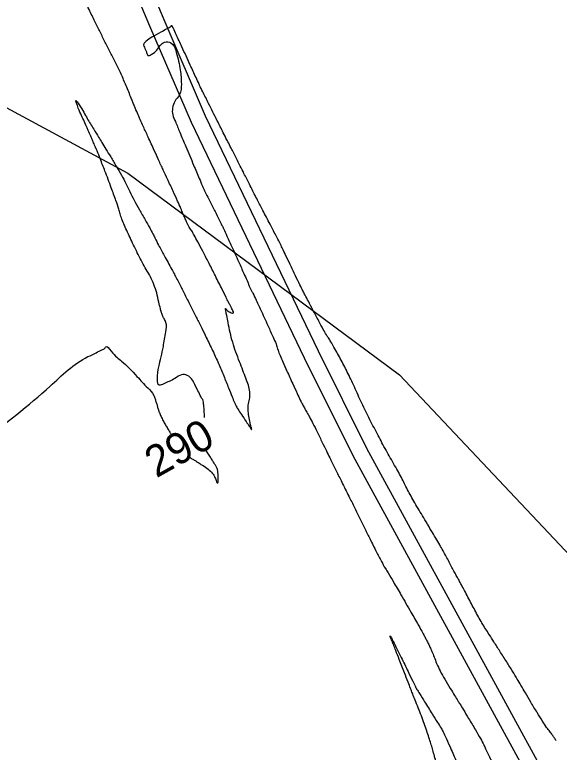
# Model space of a CAD drawing. Extents: x -478464 to -472469, y -1118040 to -1113785.
# Drawn here: x -473768.3 to -473698.4, y -1115256.6 to -1115161.8 of the extents above; entities that cross this region are included whole.
import ezdxf

# ---------------------------------------------------------------- set-up
doc = ezdxf.new("R2010")
doc.units = 0
for name, color, linetype in [('povodí', 7, 'Continuous'), ('Vrstevnice_hlavni', 7, 'Continuous'), ('Vrstevnice_popis', 7, 'Continuous'), ('Vrstevnice_vedlejsi', 7, 'Continuous'), ('zeleznice', 7, 'Continuous')]:
    doc.layers.add(name, color=color, linetype=linetype)

msp = doc.modelspace()

# ---------------------------------------------------------------- linework, layer by layer
at = {"layer": 'povodí'}
msp.add_lwpolyline([(-473844.074, -1115133.113), (-473798.595, -1115157.979), (-473753.827, -1115182.142), (-473718.927, -1115208.057), (-473688.451, -1115240.411), (-473657.186, -1115285.18), (-473633.731, -1115322.134), (-473615.258, -1115360.506), (-473588.963, -1115399.592), (-473556.984, -1115431.571), (-473519.322, -1115462.835), (-473482.374, -1115487.707), (-473442.476, -1115513.736), (-473401.772, -1115547.685), (-473399.446, -1115558.069), (-473399.04, -1115611.279), (-473399.18, -1115635.636), (-473402.808, -1115682.163), (-473408.691, -1115743.551), (-473409.522, -1115757.251)], dxfattribs=at)
at = {"layer": 'Vrstevnice_hlavni'}
for points in [[(-473738.005, -1115215.005), (-473737.987, -1115215.045), (-473737.969, -1115215.068), (-473737.952, -1115215.074), (-473737.937, -1115215.063), (-473737.988, -1115214.775), (-473738.106, -1115214.212), (-473738.291, -1115213.373), (-473738.363, -1115212.562), (-473738.323, -1115211.78), (-473738.169, -1115211.027), (-473738.174, -1115210.232), (-473738.339, -1115209.396), (-473738.664, -1115208.517), (-473739.04, -1115207.516), (-473739.469, -1115206.391), (-473739.95, -1115205.143), (-473740.354, -1115203.889), (-473740.683, -1115202.629), (-473740.935, -1115201.362), (-473741.118, -1115200.454), (-473741.23, -1115199.905), (-473741.271, -1115199.715), (-473741.29, -1115199.592), (-473741.287, -1115199.535), (-473741.262, -1115199.543), (-473741.218, -1115199.589), (-473741.156, -1115199.67), (-473741.075, -1115199.788), (-473740.92, -1115199.909), (-473740.69, -1115200.032), (-473740.385, -1115200.158), (-473740.262, -1115200.089), (-473740.323, -1115199.826), (-473740.566, -1115199.369), (-473740.742, -1115199.035), (-473740.852, -1115198.824), (-473740.894, -1115198.737), (-473741.213, -1115198.096), (-473741.808, -1115196.9), (-473742.68, -1115195.149), (-473743.474, -1115193.58), (-473744.192, -1115192.193), (-473744.834, -1115190.987), (-473745.31, -1115190.114), (-473745.62, -1115189.574), (-473745.765, -1115189.367), (-473745.924, -1115189.101), (-473746.097, -1115188.777), (-473746.283, -1115188.395), (-473746.498, -1115187.92), (-473746.741, -1115187.354), (-473747.013, -1115186.695), (-473747.433, -1115185.738), (-473748.002, -1115184.482), (-473748.718, -1115182.927), (-473749.218, -1115181.847), (-473749.501, -1115181.242), (-473749.568, -1115181.111), (-473749.874, -1115180.45), (-473750.419, -1115179.257), (-473751.204, -1115177.533), (-473751.811, -1115176.196), (-473752.238, -1115175.246), (-473752.486, -1115174.683), (-473752.868, -1115173.776), (-473753.383, -1115172.525), (-473754.032, -1115170.93), (-473754.692, -1115169.426), (-473755.363, -1115168.011), (-473756.045, -1115166.686), (-473756.718, -1115165.355), (-473757.382, -1115164.019), (-473758.037, -1115162.676), (-473758.789, -1115161.143), (-473759.637, -1115159.421), (-473760.583, -1115157.51), (-473761.352, -1115155.886), (-473761.944, -1115154.549), (-473762.359, -1115153.498), (-473762.79, -1115152.482), (-473763.236, -1115151.499), (-473763.697, -1115150.551), (-473764.022, -1115149.64), (-473764.211, -1115148.769), (-473764.265, -1115147.936), (-473764.421, -1115147.071), (-473764.68, -1115146.175), (-473765.043, -1115145.248), (-473765.342, -1115144.414), (-473765.578, -1115143.673), (-473765.75, -1115143.024), (-473765.97, -1115142.449), (-473766.238, -1115141.948), (-473766.554, -1115141.52), (-473766.5, -1115141.051), (-473766.077, -1115140.542)], [(-473747.97, -1115163.564), (-473747.976, -1115163.551), (-473748, -1115163.501), (-473748.042, -1115163.413), (-473748.103, -1115163.289), (-473748.168, -1115163.234), (-473748.238, -1115163.248), (-473748.313, -1115163.331), (-473748.757, -1115163.601), (-473749.57, -1115164.059), (-473750.753, -1115164.703), (-473751.5, -1115165.24), (-473751.811, -1115165.669), (-473751.687, -1115165.99), (-473751.551, -1115166.323), (-473751.404, -1115166.671), (-473751.246, -1115167.031), (-473750.811, -1115166.929), (-473750.099, -1115166.365), (-473749.111, -1115165.339), (-473748.28, -1115165.42), (-473747.607, -1115166.608), (-473747.091, -1115168.903), (-473746.948, -1115170.723), (-473747.18, -1115172.068), (-473747.785, -1115172.937), (-473748.077, -1115173.8), (-473748.055, -1115174.658), (-473747.719, -1115175.509), (-473747.16, -1115176.874), (-473746.377, -1115178.75), (-473745.37, -1115181.139), (-473744.656, -1115182.83), (-473744.236, -1115183.824), (-473744.11, -1115184.12), (-473743.798, -1115184.765), (-473743.3, -1115185.76), (-473742.616, -1115187.103), (-473742.093, -1115188.138), (-473741.73, -1115188.864), (-473741.529, -1115189.281), (-473741.088, -1115190.237), (-473740.409, -1115191.731), (-473739.49, -1115193.764), (-473738.826, -1115195.248), (-473738.418, -1115196.183), (-473738.265, -1115196.568), (-473738.105, -1115196.931), (-473737.939, -1115197.271), (-473737.767, -1115197.589), (-473737.34, -1115198.479), (-473736.66, -1115199.94), (-473735.725, -1115201.973), (-473735.076, -1115203.426), (-473734.712, -1115204.301), (-473734.633, -1115204.596), (-473734.534, -1115204.912), (-473734.413, -1115205.248), (-473734.271, -1115205.604), (-473733.931, -1115206.384), (-473733.39, -1115207.587), (-473732.651, -1115209.213), (-473732.077, -1115210.457), (-473731.669, -1115211.319), (-473731.426, -1115211.799), (-473731.151, -1115212.316), (-473730.843, -1115212.872), (-473730.503, -1115213.466), (-473730.058, -1115214.309), (-473729.509, -1115215.402), (-473728.855, -1115216.744), (-473728.314, -1115217.853), (-473727.888, -1115218.728), (-473727.574, -1115219.37), (-473727.061, -1115220.407), (-473726.347, -1115221.841), (-473725.434, -1115223.67), (-473724.713, -1115225.122), (-473724.184, -1115226.195), (-473723.848, -1115226.89), (-473723.357, -1115227.886), (-473722.711, -1115229.183), (-473721.911, -1115230.781), (-473721.258, -1115232.038), (-473720.75, -1115232.953), (-473720.388, -1115233.527), (-473719.719, -1115234.653), (-473718.744, -1115236.332), (-473717.461, -1115238.564), (-473716.525, -1115240.203), (-473715.936, -1115241.249), (-473715.693, -1115241.702), (-473715.459, -1115242.152), (-473715.234, -1115242.597), (-473715.018, -1115243.039), (-473714.767, -1115243.614), (-473714.482, -1115244.321)], [(-473698.836, -1115255.061), (-473699.092, -1115254.651), (-473699.314, -1115254.335), (-473699.628, -1115253.907), (-473700.037, -1115253.369), (-473700.579, -1115252.557), (-473701.256, -1115251.469), (-473702.068, -1115250.108), (-473702.764, -1115248.933), (-473703.344, -1115247.947), (-473703.809, -1115247.148), (-473704.416, -1115246.149), (-473705.167, -1115244.951), (-473706.06, -1115243.553), (-473706.811, -1115242.378), (-473707.419, -1115241.427), (-473707.884, -1115240.699), (-473708.345, -1115239.938), (-473708.801, -1115239.145), (-473709.253, -1115238.319), (-473709.7, -1115237.485), (-473710.143, -1115236.642), (-473710.581, -1115235.792), (-473710.965, -1115235.064), (-473711.292, -1115234.46), (-473711.565, -1115233.979), (-473711.865, -1115233.428), (-473712.194, -1115232.808), (-473712.551, -1115232.118), (-473712.932, -1115231.406), (-473713.338, -1115230.672), (-473713.768, -1115229.916), (-473714.274, -1115229.048), (-473714.857, -1115228.065), (-473715.515, -1115226.97), (-473716.128, -1115225.942), (-473716.694, -1115224.981), (-473717.215, -1115224.086), (-473717.685, -1115223.238), (-473718.107, -1115222.437), (-473718.479, -1115221.682), (-473718.915, -1115220.852), (-473719.416, -1115219.948), (-473719.982, -1115218.968), (-473720.529, -1115218), (-473721.055, -1115217.041), (-473721.561, -1115216.092), (-473722.076, -1115215.109), (-473722.599, -1115214.092), (-473723.131, -1115213.04), (-473723.643, -1115211.985), (-473724.136, -1115210.927), (-473724.61, -1115209.867), (-473725.073, -1115208.866), (-473725.526, -1115207.927), (-473725.968, -1115207.047), (-473726.418, -1115206.186), (-473726.878, -1115205.343), (-473727.347, -1115204.518), (-473727.742, -1115203.844), (-473728.063, -1115203.322), (-473728.312, -1115202.95), (-473728.726, -1115202.228), (-473729.305, -1115201.154), (-473730.05, -1115199.728), (-473730.633, -1115198.615), (-473731.055, -1115197.815), (-473731.315, -1115197.327), (-473731.722, -1115196.508), (-473732.277, -1115195.359), (-473732.98, -1115193.879), (-473733.552, -1115192.68), (-473733.994, -1115191.764), (-473734.307, -1115191.129), (-473734.826, -1115190.113), (-473735.553, -1115188.716), (-473736.486, -1115186.939), (-473737.166, -1115185.636), (-473737.592, -1115184.809), (-473737.764, -1115184.457), (-473738.202, -1115183.586), (-473738.906, -1115182.196), (-473739.875, -1115180.287), (-473740.564, -1115178.93), (-473740.973, -1115178.126), (-473741.102, -1115177.874), (-473741.557, -1115176.971), (-473742.338, -1115175.418), (-473743.446, -1115173.214), (-473744.203, -1115171.702), (-473744.609, -1115170.881), (-473744.664, -1115170.751), (-473745.062, -1115169.882), (-473745.802, -1115168.273), (-473746.883, -1115165.925), (-473747.606, -1115164.356), (-473747.97, -1115163.564)], [(-473743.98, -1115213.556), (-473744.057, -1115212.082), (-473744.11, -1115211.561), (-473744.179, -1115211.253), (-473744.263, -1115211.161), (-473744.514, -1115210.714), (-473744.932, -1115209.911), (-473745.518, -1115208.752), (-473746.186, -1115208.136), (-473746.936, -1115208.064), (-473747.768, -1115208.534), (-473748.523, -1115208.914), (-473749.201, -1115209.206), (-473749.801, -1115209.409), (-473750.012, -1115208.682), (-473749.831, -1115207.027), (-473749.26, -1115204.442), (-473748.96, -1115202.549), (-473748.931, -1115201.348), (-473749.174, -1115200.84), (-473749.351, -1115200.455), (-473749.463, -1115200.192), (-473749.51, -1115200.053), (-473749.634, -1115199.567), (-473749.836, -1115198.734), (-473750.115, -1115197.554), (-473750.478, -1115196.462), (-473750.925, -1115195.458), (-473751.457, -1115194.543), (-473751.974, -1115193.6), (-473752.478, -1115192.628), (-473752.968, -1115191.629), (-473753.428, -1115190.67), (-473753.858, -1115189.751), (-473754.258, -1115188.872), (-473754.577, -1115188.087), (-473754.815, -1115187.397), (-473754.972, -1115186.803), (-473755.348, -1115185.686), (-473755.945, -1115184.047), (-473756.76, -1115181.886), (-473757.367, -1115180.306), (-473757.763, -1115179.309), (-473757.951, -1115178.895), (-473758.102, -1115178.543), (-473758.218, -1115178.254), (-473758.298, -1115178.028), (-473758.382, -1115177.815), (-473758.47, -1115177.614), (-473758.563, -1115177.426), (-473758.899, -1115176.675), (-473759.479, -1115175.362), (-473760.301, -1115173.487), (-473760.501, -1115172.823), (-473760.078, -1115173.37), (-473759.032, -1115175.128), (-473758.197, -1115176.522), (-473757.573, -1115177.554), (-473757.16, -1115178.222), (-473756.642, -1115179.064), (-473756.021, -1115180.079), (-473755.295, -1115181.268), (-473754.646, -1115182.405), (-473754.073, -1115183.491), (-473753.577, -1115184.525), (-473752.997, -1115185.649), (-473752.335, -1115186.863), (-473751.591, -1115188.167), (-473751.012, -1115189.204), (-473750.599, -1115189.975), (-473750.351, -1115190.48), (-473749.865, -1115191.407), (-473749.14, -1115192.754), (-473748.177, -1115194.523), (-473747.509, -1115195.761), (-473747.136, -1115196.467), (-473747.059, -1115196.642), (-473746.77, -1115197.229), (-473746.268, -1115198.229), (-473745.554, -1115199.642), (-473745.046, -1115200.642), (-473744.745, -1115201.228), (-473744.65, -1115201.401), (-473744.316, -1115202.081), (-473743.743, -1115203.268), (-473742.931, -1115204.962), (-473742.184, -1115206.607), (-473741.502, -1115208.206), (-473740.884, -1115209.756), (-473740.425, -1115210.896), (-473740.125, -1115211.625), (-473739.984, -1115211.944), (-473739.688, -1115212.457), (-473739.237, -1115213.164), (-473738.63, -1115214.064), (-473738.22, -1115214.678), (-473738.005, -1115215.005)], [(-473925.982, -1115349.51), (-473924.531, -1115349.642), (-473923.767, -1115349.62), (-473922.965, -1115349.51), (-473922.125, -1115349.312), (-473921.523, -1115349.215), (-473921.16, -1115349.217), (-473921.035, -1115349.319), (-473920.467, -1115349.233), (-473919.456, -1115348.959), (-473918.001, -1115348.498), (-473916.354, -1115347.955), (-473914.517, -1115347.331), (-473912.488, -1115346.626), (-473911.093, -1115346.095), (-473910.331, -1115345.74), (-473910.202, -1115345.559), (-473909.998, -1115345.271), (-473909.718, -1115344.878), (-473909.362, -1115344.38), (-473908.597, -1115343.556), (-473907.423, -1115342.407), (-473905.84, -1115340.932), (-473902.875, -1115338.099), (-473898.529, -1115333.908), (-473892.8, -1115328.358), (-473888.715, -1115324.402), (-473886.274, -1115322.042), (-473885.477, -1115321.277), (-473884.754, -1115320.63), (-473884.105, -1115320.1), (-473883.53, -1115319.689), (-473883.1, -1115319.337), (-473882.814, -1115319.044), (-473882.674, -1115318.811), (-473882.298, -1115318.452), (-473881.688, -1115317.968), (-473880.844, -1115317.358), (-473878.656, -1115315.687), (-473875.123, -1115312.955), (-473870.245, -1115309.161), (-473864.175, -1115304.583), (-473856.912, -1115299.218), (-473848.456, -1115293.068), (-473841.691, -1115288.2), (-473836.618, -1115284.612), (-473833.235, -1115282.306), (-473829.085, -1115279.347), (-473824.167, -1115275.735), (-473818.48, -1115271.471), (-473813.304, -1115265.605), (-473808.638, -1115258.137), (-473804.481, -1115249.069), (-473801.7, -1115242.997), (-473800.293, -1115239.924), (-473800.261, -1115239.847), (-473800.214, -1115239.776), (-473800.153, -1115239.711), (-473800.076, -1115239.65), (-473799.737, -1115239.367), (-473799.134, -1115238.861), (-473798.268, -1115238.132), (-473793.535, -1115234.182), (-473784.935, -1115227.013), (-473772.468, -1115216.623), (-473763.801, -1115209.53), (-473758.937, -1115205.733), (-473757.873, -1115205.232), (-473757.14, -1115204.855), (-473756.737, -1115204.601), (-473756.664, -1115204.47), (-473755.957, -1115205.039), (-473754.617, -1115206.308), (-473752.642, -1115208.277), (-473751.269, -1115209.743), (-473750.495, -1115210.706), (-473750.321, -1115211.165), (-473750.17, -1115211.612), (-473750.042, -1115212.046), (-473749.935, -1115212.467), (-473749.772, -1115212.928), (-473749.552, -1115213.429), (-473749.276, -1115213.969), (-473748.996, -1115214.482), (-473748.715, -1115214.969), (-473748.432, -1115215.429), (-473748.242, -1115215.736), (-473748.147, -1115215.891), (-473748.146, -1115215.893)], [(-473745.8, -1115218.705), (-473745.785, -1115218.72), (-473745.714, -1115218.763), (-473745.581, -1115218.842), (-473745.386, -1115218.958), (-473745, -1115219.2), (-473744.424, -1115219.57), (-473743.657, -1115220.067), (-473743.08, -1115220.581), (-473742.693, -1115221.112), (-473742.494, -1115221.66), (-473742.352, -1115221.94), (-473742.265, -1115221.954), (-473742.234, -1115221.702), (-473742.22, -1115221.393), (-473742.222, -1115221.029), (-473742.241, -1115220.609), (-473742.324, -1115220.215), (-473742.47, -1115219.847), (-473742.681, -1115219.505), (-473742.93, -1115219.107), (-473743.219, -1115218.651), (-473743.875, -1115217.625)], [(-473714.482, -1115244.321), (-473714.162, -1115245.162), (-473713.71, -1115246.114), (-473713.128, -1115247.178), (-473712.413, -1115248.353), (-473711.852, -1115249.272), (-473711.445, -1115249.935), (-473711.191, -1115250.341), (-473710.73, -1115251.099), (-473710.063, -1115252.21), (-473709.188, -1115253.675), (-473708.535, -1115254.812), (-473708.101, -1115255.622), (-473707.889, -1115256.105), (-473707.385, -1115257.152), (-473706.591, -1115258.761), (-473705.506, -1115260.932), (-473704.723, -1115262.516), (-473704.242, -1115263.511), (-473704.064, -1115263.918), (-473703.866, -1115264.324), (-473703.65, -1115264.729), (-473703.414, -1115265.133), (-473702.981, -1115265.874), (-473702.348, -1115266.952), (-473701.518, -1115268.368), (-473700.773, -1115269.643), (-473700.114, -1115270.777), (-473699.541, -1115271.77), (-473699.023, -1115272.655), (-473698.56, -1115273.433), (-473698.152, -1115274.103), (-473697.582, -1115275.039), (-473696.85, -1115276.24), (-473695.955, -1115277.707), (-473695.239, -1115278.888), (-473694.7, -1115279.782), (-473694.34, -1115280.39), (-473694.084, -1115280.823), (-473693.933, -1115281.082), (-473693.84, -1115281.249)]]:
    msp.add_spline(points, degree=3, dxfattribs=at)
at = {"layer": 'Vrstevnice_vedlejsi'}
msp.add_spline([(-473724.232, -1115273.019), (-473724.392, -1115273.767), (-473724.278, -1115274.455), (-473723.889, -1115275.085), (-473723.225, -1115275.655), (-473722.84, -1115275.716), (-473722.735, -1115275.267), (-473722.91, -1115274.308), (-473723.04, -1115273.592), (-473723.126, -1115273.119), (-473723.167, -1115272.888), (-473722.992, -1115272.63), (-473722.599, -1115272.347), (-473721.989, -1115272.037), (-473721.55, -1115271.791), (-473721.284, -1115271.61), (-473721.189, -1115271.494), (-473721.036, -1115271.174), (-473720.824, -1115270.649), (-473720.554, -1115269.921), (-473720.362, -1115269.371), (-473720.25, -1115268.999), (-473720.215, -1115268.804), (-473720.158, -1115268.38), (-473720.077, -1115267.726), (-473719.974, -1115266.843), (-473719.667, -1115266.336), (-473719.157, -1115266.205), (-473718.445, -1115266.45), (-473717.595, -1115266.619), (-473716.61, -1115266.711), (-473715.487, -1115266.727), (-473714.697, -1115266.414), (-473714.24, -1115265.772), (-473714.116, -1115264.803), (-473714.026, -1115263.961), (-473713.971, -1115263.247), (-473713.95, -1115262.661), (-473713.932, -1115262.1), (-473713.915, -1115261.563), (-473713.901, -1115261.052), (-473713.875, -1115260.652), (-473713.836, -1115260.364), (-473713.785, -1115260.186), (-473713.831, -1115259.727), (-473713.976, -1115258.984), (-473714.219, -1115257.959), (-473714.446, -1115257.057), (-473714.657, -1115256.279), (-473714.853, -1115255.624), (-473715.089, -1115254.878), (-473715.365, -1115254.042), (-473715.682, -1115253.116), (-473716.034, -1115252.146), (-473716.422, -1115251.132), (-473716.846, -1115250.074), (-473717.169, -1115249.258), (-473717.393, -1115248.684), (-473717.518, -1115248.353), (-473717.82, -1115247.57), (-473718.3, -1115246.336), (-473718.958, -1115244.651), (-473719.417, -1115243.476), (-473719.675, -1115242.81), (-473719.734, -1115242.654), (-473719.827, -1115242.419), (-473719.953, -1115242.104), (-473720.113, -1115241.709), (-473720.146, -1115241.584), (-473720.052, -1115241.728), (-473719.83, -1115242.141), (-473719.385, -1115243.024), (-473718.717, -1115244.376), (-473717.825, -1115246.198), (-473717.222, -1115247.436), (-473716.906, -1115248.091), (-473716.879, -1115248.163), (-473716.841, -1115248.244), (-473716.791, -1115248.334), (-473716.73, -1115248.434), (-473716.368, -1115249.016), (-473715.703, -1115250.08), (-473714.736, -1115251.626), (-473714.035, -1115252.75), (-473713.601, -1115253.452), (-473713.434, -1115253.732), (-473713.062, -1115254.511), (-473712.485, -1115255.788), (-473711.703, -1115257.564), (-473711.089, -1115258.933), (-473710.643, -1115259.896), (-473710.365, -1115260.453), (-473709.968, -1115261.306), (-473709.452, -1115262.455), (-473708.817, -1115263.9), (-473708.116, -1115265.341), (-473707.348, -1115266.779)], degree=3, dxfattribs=at)
at = {"layer": 'zeleznice'}
for points in [[(-473821.511, -1114713.064), (-473823.854, -1114740.344), (-473825.231, -1114762.204), (-473826.196, -1114799.127), (-473824.451, -1114860.023), (-473823.348, -1114876.556), (-473821.787, -1114889.277), (-473821.197, -1114898.123), (-473818.71, -1114917.245), (-473815.909, -1114938.783), (-473811.729, -1114964.226), (-473808.055, -1114983.56), (-473802.131, -1115010.058), (-473793.497, -1115043.767), (-473785.544, -1115071.598), (-473782.384, -1115080.828), (-473772.442, -1115109.867), (-473766.103, -1115126.707), (-473763.83, -1115132.746), (-473751.017, -1115163.217), (-473745.69, -1115175.616), (-473731.178, -1115205.88), (-473724.932, -1115218.418), (-473701.171, -1115261.995)], [(-473819.519, -1114713.235), (-473821.859, -1114740.492), (-473823.233, -1114762.293), (-473824.195, -1114799.124), (-473822.452, -1114859.928), (-473821.356, -1114876.367), (-473819.795, -1114889.088), (-473819.206, -1114897.927), (-473816.727, -1114916.987), (-473813.93, -1114938.492), (-473809.76, -1114963.877), (-473806.097, -1114983.155), (-473800.186, -1115009.592), (-473791.567, -1115043.244), (-473783.635, -1115070.999), (-473780.491, -1115080.18), (-473770.56, -1115109.191), (-473764.232, -1115126.002), (-473761.972, -1115132.005), (-473749.177, -1115162.434), (-473743.869, -1115174.789), (-473729.381, -1115205.002), (-473723.158, -1115217.493), (-473699.45, -1115260.975)]]:
    msp.add_lwpolyline(points, dxfattribs=at)

# ---------------------------------------------------------------- texts
at = {"layer": 'Vrstevnice_popis'}
msp.add_text(' 290 ', height=4, rotation=29.29257, dxfattribs=at).set_placement((-473751.459, -1115222.109))

doc.saveas('drawing.dxf')
